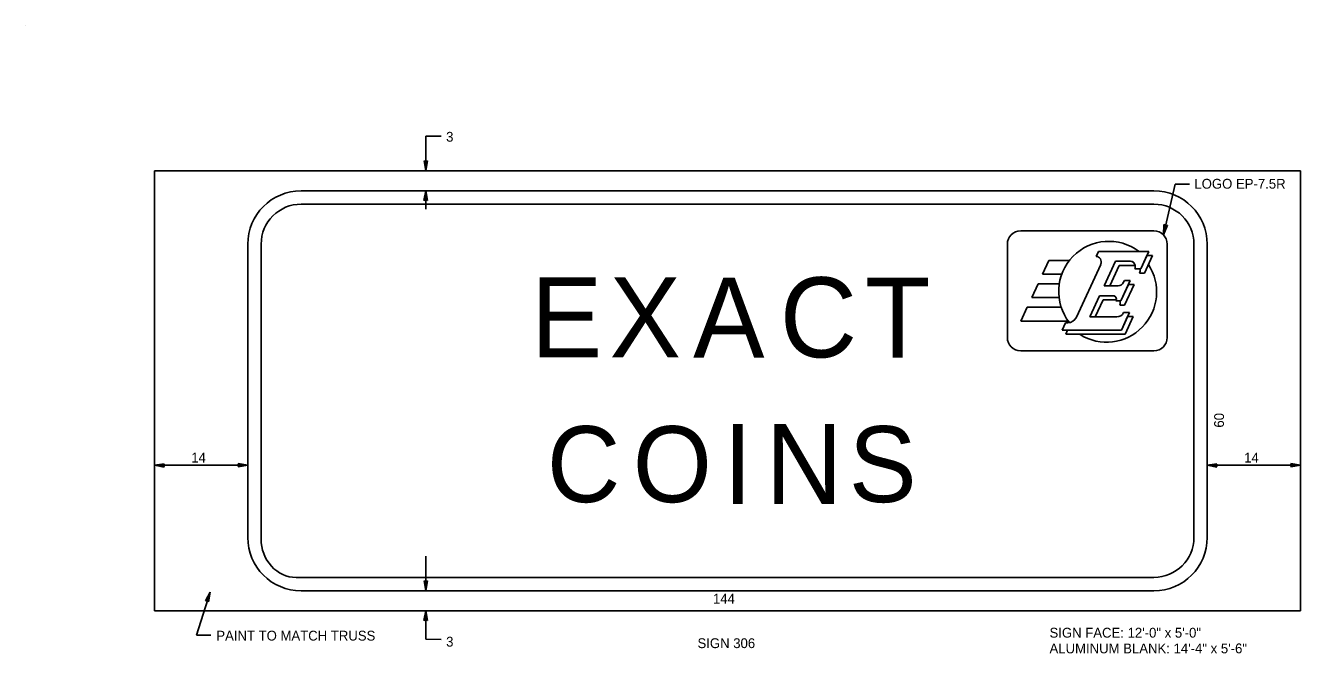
# Model space of a CAD drawing. Extents: x 60714 to 61340, y 9180 to 9758.
# Drawn here: x 60713.6 to 61077.2, y 9180 to 9359 of the extents above; entities that cross this region are included whole.
import ezdxf

# ---------------------------------------------------------------- set-up
doc = ezdxf.new("R2010")
doc.units = 0
for name, color, linetype in [('1', 7, 'Continuous'), ('2', 7, 'Continuous'), ('3', 7, 'Continuous'), ('52', 7, 'Continuous'), ('AdhocPoint_dp', 7, 'Continuous')]:
    doc.layers.add(name, color=color, linetype=linetype)

msp = doc.modelspace()

# ---------------------------------------------------------------- linework, layer by layer
at = {"layer": '1'}
for p, q in [((60827.74, 9327.43), (60832.14, 9327.4)), ((60827.74, 9317.54), (60827.74, 9327.43)), ((60827.74, 9306.64), (60827.74, 9311.84)), ((61038.07, 9299.32), (61041.4, 9313.74)), ((61041.4, 9313.74), (61045.54, 9313.74)), ((60750.38, 9233.62), (60776.98, 9233.62)), ((61050.58, 9233.62), (61077.18, 9233.62)), ((60827.74, 9197.84), (60827.74, 9207.73)), ((60762.33, 9185.21), (60766.24, 9197.45)), ((60827.74, 9184.03), (60827.74, 9192.14)), ((60762.33, 9185.21), (60766.44, 9185.18)), ((60827.74, 9184.03), (60832.14, 9184))]:
    msp.add_line(p, q, dxfattribs=at)
at = {"layer": '2'}
for p, q in [((60750.38, 9192.14), (60750.38, 9317.54)), ((60750.38, 9317.54), (61077.18, 9317.54)), ((61077.18, 9192.14), (61077.18, 9317.54)), ((60792.18, 9311.84), (61035.38, 9311.84)), ((60792.18, 9308.04), (61035.38, 9308.04)), ((60997.38, 9300.44), (61035.38, 9300.44)), ((60776.98, 9213.04), (60776.98, 9296.64)), ((60780.78, 9212.64), (60780.78, 9296.64)), ((60993.58, 9270.04), (60993.58, 9296.64)), ((61019.53, 9294.56), (61018.88, 9293.16)), ((61019.53, 9294.56), (61033.91, 9294.56)), ((61033.91, 9294.56), (61031.61, 9289.57)), ((61039.18, 9270.04), (61039.18, 9296.64)), ((61046.78, 9213.04), (61046.78, 9296.64)), ((61050.58, 9213.04), (61050.58, 9296.64)), ((61005.43, 9292.01), (61003.61, 9288.08)), ((61011.29, 9292.01), (61005.43, 9292.01)), ((61013.27, 9275.88), (61020.2, 9290.88)), ((61024.4, 9291.76), (61021.17, 9284.76)), ((61025.46, 9290.58), (61022.77, 9284.76)), ((61028.72, 9291.76), (61024.4, 9291.76)), ((61030.04, 9290.58), (61025.46, 9290.58)), ((61034.97, 9293.38), (61032.66, 9288.39)), ((61033.37, 9293.38), (61034.97, 9293.38)), ((61009.09, 9288.08), (61003.61, 9288.08)), ((61028.65, 9286.27), (61025.96, 9280.45)), ((61026.95, 9286.27), (61026.73, 9285.78)), ((61026.95, 9286.27), (61028.65, 9286.27)), ((61031.61, 9289.57), (61029.91, 9289.57)), ((61031.27, 9288.39), (61032.66, 9288.39)), ((61002.34, 9285.33), (61000.53, 9281.4)), ((61008.38, 9285.33), (61002.34, 9285.33)), ((61021.17, 9284.76), (61025.22, 9284.76)), ((61029.7, 9285.1), (61027.01, 9279.27)), ((61028.1, 9285.1), (61029.7, 9285.1)), ((61008.32, 9281.4), (61000.53, 9281.4)), ((61019.88, 9281.96), (61017.07, 9275.9)), ((61020.93, 9280.79), (61018.67, 9275.9)), ((61023.78, 9281.96), (61019.88, 9281.96)), ((61024.65, 9280.79), (61020.93, 9280.79)), ((61024.53, 9280.45), (61025.96, 9280.45)), ((61027.01, 9279.27), (61025.62, 9279.27)), ((60999.25, 9278.65), (60997.44, 9274.72)), ((61008.94, 9278.65), (60999.25, 9278.65)), ((61017.07, 9275.9), (61024.84, 9275.9)), ((61028.41, 9277.16), (61026.1, 9272.17)), ((61026.72, 9277.16), (61028.41, 9277.16)), ((61029.46, 9275.98), (61027.16, 9270.99)), ((61027.86, 9275.98), (61029.46, 9275.98)), ((60997.44, 9274.72), (61010.95, 9274.72)), ((61009.18, 9272.17), (61010.14, 9274.25)), ((61026.1, 9272.17), (61009.18, 9272.17)), ((61010.14, 9274.25), (61010.85, 9274.25)), ((61010.24, 9270.99), (61010.78, 9272.17)), ((61027.16, 9270.99), (61010.24, 9270.99)), ((60997.38, 9266.24), (61035.38, 9266.24)), ((60790.76, 9201.64), (61035.38, 9201.64)), ((60792.18, 9197.84), (61035.38, 9197.84)), ((60750.38, 9192.14), (61077.18, 9192.14))]:
    msp.add_line(p, q, dxfattribs=at)
for centre, radius, start, end in [((60792.18, 9296.64), 15.2, 90, 180), ((61035.38, 9296.64), 15.2, 0, 90), ((60792.18, 9296.64), 11.4, 90, 180), ((61035.38, 9296.64), 11.4, 0, 90), ((60997.38, 9296.64), 3.8, 90, 180), ((61022.52, 9283.14), 14.31, 52.9547, 218.1763), ((61035.38, 9296.64), 3.8, 0, 90), ((61021.85, 9283.02), 14.31, 238.1578, 33.3171), ((60997.38, 9270.04), 3.8, 180, 270), ((61035.38, 9270.04), 3.8, 270, 360), ((60792.18, 9213.04), 15.2, 180, 270), ((61035.38, 9213.04), 11.4, 270, 0), ((61035.38, 9213.04), 15.2, 270, 0)]:
    msp.add_arc(centre, radius, start, end, dxfattribs=at)
for centre, major_axis, start_param, end_param in [((61018.92, 9291.59), (0, 1.57), 4.241328, 6.314398), ((61028.72, 9290.27), (0, 1.49), 4.227342, 6.283185), ((61030.07, 9289.09), (0, 1.49), 4.227342, 5.041732), ((61025.22, 9286.63), (0, 1.87), 3.141593, 4.241405), ((61023.78, 9280.98), (0, 0.982), 4.144801, 6.283185), ((61024.42, 9279.97), (0, 1.49), 4.227342, 5.041732), ((61010.85, 9277.23), (0, 2.99), 3.141593, 4.241135), ((61024.84, 9278.23), (0, 2.33), 3.141593, 4.232591), ((60790.75, 9212.64), (0, 11), 1.570796, 3.141593)]:
    msp.add_ellipse(centre, major_axis=major_axis, ratio=0.906668, start_param=start_param, end_param=end_param, dxfattribs=at)
at = {"layer": '3'}
for p, q in [((61024.4, 9291.76), (61021.17, 9284.76)), ((61022.77, 9284.76), (61025.46, 9290.58)), ((61028.72, 9291.76), (61024.4, 9291.76)), ((61025.46, 9290.58), (61030.04, 9290.58)), ((61031.61, 9289.57), (61033.37, 9293.38)), ((61034.97, 9293.38), (61032.66, 9288.39)), ((61033.37, 9293.38), (61034.97, 9293.38)), ((61032.66, 9288.39), (61031.27, 9288.39)), ((61031.35, 9289.57), (61031.61, 9289.57)), ((61021.17, 9284.76), (61022.77, 9284.76)), ((61025.96, 9280.45), (61028.1, 9285.1)), ((61029.7, 9285.1), (61027.01, 9279.27)), ((61028.1, 9285.1), (61029.7, 9285.1)), ((61019.88, 9281.96), (61017.07, 9275.9)), ((61018.67, 9275.9), (61020.93, 9280.79)), ((61023.78, 9281.96), (61019.88, 9281.96)), ((61020.93, 9280.79), (61024.65, 9280.79)), ((61027.01, 9279.27), (61025.62, 9279.27)), ((61025.71, 9280.45), (61025.96, 9280.45)), ((61017.07, 9275.9), (61017.07, 9275.9)), ((61017.07, 9275.9), (61018.67, 9275.9)), ((61026.1, 9272.17), (61027.86, 9275.98)), ((61029.46, 9275.98), (61027.16, 9270.99)), ((61027.86, 9275.98), (61029.46, 9275.98)), ((61010.24, 9270.99), (61010.78, 9272.17)), ((61010.78, 9272.17), (61026.1, 9272.17)), ((61027.16, 9270.99), (61010.24, 9270.99))]:
    msp.add_line(p, q, dxfattribs=at)
for centre, major_axis, start_param, end_param in [((61028.72, 9290.27), (0, 1.49), 4.924772, 6.283185), ((61030.07, 9289.09), (0, 1.49), 4.227342, 5.041732), ((61023.78, 9280.98), (0, 0.982), 4.511031, 6.283185), ((61024.42, 9279.97), (0, 1.49), 4.227342, 5.041732)]:
    msp.add_ellipse(centre, major_axis=major_axis, ratio=0.906668, start_param=start_param, end_param=end_param, dxfattribs=at)
at = {"layer": '52'}
for p, q in [((60827.72, 9317.62), (60827.28, 9320.39)), ((60827.77, 9320.17), (60827.28, 9320.39)), ((60827.72, 9317.62), (60827.54, 9320.28)), ((60827.72, 9317.62), (60828.26, 9320.38)), ((60827.72, 9317.62), (60828, 9320.27)), ((60828.26, 9320.38), (60827.77, 9320.17)), ((60827.74, 9311.84), (60827.2, 9309.08)), ((60827.74, 9311.84), (60827.46, 9309.18)), ((60827.74, 9311.84), (60828.18, 9309.06)), ((60827.74, 9311.84), (60827.92, 9309.18)), ((60827.2, 9309.08), (60827.69, 9309.28)), ((60827.69, 9309.28), (60828.18, 9309.06)), ((61038.07, 9299.32), (61038.22, 9302.28)), ((61038.07, 9299.32), (61038.46, 9302.1)), ((61038.07, 9299.32), (61039.23, 9302.05)), ((61038.07, 9299.32), (61038.94, 9302)), ((61038.67, 9301.95), (61038.22, 9302.28)), ((61039.23, 9302.05), (61038.67, 9301.95)), ((60750.38, 9233.62), (60753.16, 9234.06)), ((60750.38, 9233.62), (60753.04, 9233.81)), ((60750.38, 9233.62), (60753.14, 9233.08)), ((60750.38, 9233.62), (60753.03, 9233.34)), ((60752.94, 9233.58), (60753.16, 9234.06)), ((60753.14, 9233.08), (60752.94, 9233.58)), ((60774.42, 9233.66), (60774.2, 9233.18)), ((60776.98, 9233.62), (60774.2, 9233.18)), ((60776.98, 9233.62), (60774.22, 9234.16)), ((60774.22, 9234.16), (60774.42, 9233.66)), ((60776.98, 9233.62), (60774.32, 9233.43)), ((60776.98, 9233.62), (60774.33, 9233.9)), ((61050.58, 9233.62), (61053.36, 9234.06)), ((61050.58, 9233.62), (61053.24, 9233.81)), ((61050.58, 9233.62), (61053.34, 9233.08)), ((61050.58, 9233.62), (61053.23, 9233.34)), ((61053.14, 9233.58), (61053.36, 9234.06)), ((61053.34, 9233.08), (61053.14, 9233.58)), ((61074.62, 9233.66), (61074.4, 9233.18)), ((61077.18, 9233.62), (61074.4, 9233.18)), ((61077.18, 9233.62), (61074.42, 9234.16)), ((61074.42, 9234.16), (61074.62, 9233.66)), ((61077.18, 9233.62), (61074.52, 9233.43)), ((61077.18, 9233.62), (61074.53, 9233.9)), ((60827.72, 9197.92), (60827.28, 9200.69)), ((60827.77, 9200.47), (60827.28, 9200.69)), ((60827.72, 9197.92), (60827.54, 9200.58)), ((60827.72, 9197.92), (60828.26, 9200.68)), ((60827.72, 9197.92), (60828, 9200.57)), ((60828.26, 9200.68), (60827.77, 9200.47)), ((60766.24, 9197.45), (60764.89, 9194.99)), ((60766.24, 9197.45), (60765.16, 9195.01)), ((60766.24, 9197.45), (60765.6, 9194.86)), ((60766.24, 9197.45), (60765.81, 9194.67)), ((60764.89, 9194.99), (60765.42, 9195.03)), ((60765.42, 9195.03), (60765.81, 9194.67)), ((60827.74, 9192.14), (60827.2, 9189.38)), ((60827.74, 9192.14), (60827.46, 9189.48)), ((60827.74, 9192.14), (60828.18, 9189.36)), ((60827.74, 9192.14), (60827.92, 9189.48)), ((60827.2, 9189.38), (60827.69, 9189.58)), ((60827.69, 9189.58), (60828.18, 9189.36))]:
    msp.add_line(p, q, dxfattribs=at)
at = {"layer": 'AdhocPoint_dp'}
msp.add_line((60713.58, 9358.97), (60713.58, 9358.97), dxfattribs=at)

# ---------------------------------------------------------------- texts
at = {"layer": '1'}
for s, p in [('3', (60833.54, 9325.85)), ('LOGO EP-7.5R', (61046.92, 9312.46)), ('14', (60760.85, 9234.4)), ('14', (61061.12, 9234.4)), ('144', (60909.63, 9194.19)), ('PAINT TO MATCH TRUSS', (60768, 9183.65)), ('3', (60833.54, 9181.93)), ('SIGN 306', (60905.22, 9181.5))]:
    msp.add_text(s, height=2.8, dxfattribs=at).set_placement(p)
msp.add_text('60', height=2.8, rotation=90, dxfattribs=at).set_placement((61055.36, 9244.35))
at = {"layer": '2'}
for s, height, p in [('E', 22.8, (60857.75, 9264.4)), ('X', 22.8, (60880.15, 9264.39)), ('A', 22.8, (60903.98, 9264.32)), ('C', 22.8, (60928.7, 9264.39)), ('T', 22.8, (60953.01, 9264.33)), ('C', 21.66, (60862.28, 9223.11)), ('O', 21.66, (60886.79, 9223.1)), ('I', 22.8, (60912.49, 9222.56)), ('N', 22.8, (60924.59, 9222.54)), ('S', 21.66, (60948.38, 9223.11)), ('SIGN FACE: 12\'-0" x 5\'-0"', 2.8, (61005.61, 9184.49)), ('ALUMINUM BLANK: 14\'-4" x 5\'-6"', 2.8, (61005.61, 9180.01))]:
    msp.add_text(s, height=height, dxfattribs=at).set_placement(p)

doc.saveas('drawing.dxf')
